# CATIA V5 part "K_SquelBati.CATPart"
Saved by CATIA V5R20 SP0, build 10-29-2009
Part number: Squelette_bati
Publications: "Axe_pivot_1", "Axe_pivot_2", "Axe_pivot_1'", "Axe_pivot_2'", "Droite_bati_4", "Droite_bati_3", "Droite_bati_2", "Droite_bati_1"
Bounding box of the stored display mesh (mm): x -250 to 0, y 55 to 95, z -180 to 180
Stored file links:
  G:\Khaled_CFAO_2011\ST2M\ST2M_GR2\jcoetard\Khaled\CAD_CATIA\K_SquelBati.CATPart
  G:\Khaled_CFAO_2011\ST2M\ST2M_GR2\jcoetard\Khaled\CAD_CATIA\K_Squelette.CATProduct
  G:\Khaled_CFAO_2011\ST2M\ST2M_GR2\jcoetard\jcoetard\Maquette_jcoetard\Squelette General.CATPart
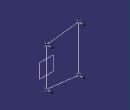
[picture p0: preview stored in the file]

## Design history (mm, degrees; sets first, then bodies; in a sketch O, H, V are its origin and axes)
Set1
  Plane1 "Plan_Ref": linked copy from another document
  Point1 to Point3: linked copy from another document
  Point4 "Point.8": linked copy from another document
Set2 "Set géométrique"
  Line1 "Axe_pivot_1": type Normal, RefPoint Point1, RefSkin Plane1, Start 0, End 40
  Line2 "Axe_pivot_2": type Normal, RefPoint Point2, RefSkin Plane1, Start 0, End 40
  Line3 "Axe_pivot_1'": type Normal, RefPoint Point3, RefSkin Plane1, Start 0, End 40
  Line4 "Axe_pivot_2'": type Normal, RefPoint Point4, RefSkin Plane1, Start 0, End 40
  Line5 "Droite_bati_1": type PtPt, FirstPoint Point1, SecondPoint Point2
  Line6 "Droite_bati_2": type PtPt, FirstPoint Point2, SecondPoint Point4
  Line7 "Droite_bati_3": type PtPt, FirstPoint Point4, SecondPoint Point3
  Line8 "Droite_bati_4": type PtPt, FirstPoint Point3, SecondPoint Point1
Body1 (main body)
